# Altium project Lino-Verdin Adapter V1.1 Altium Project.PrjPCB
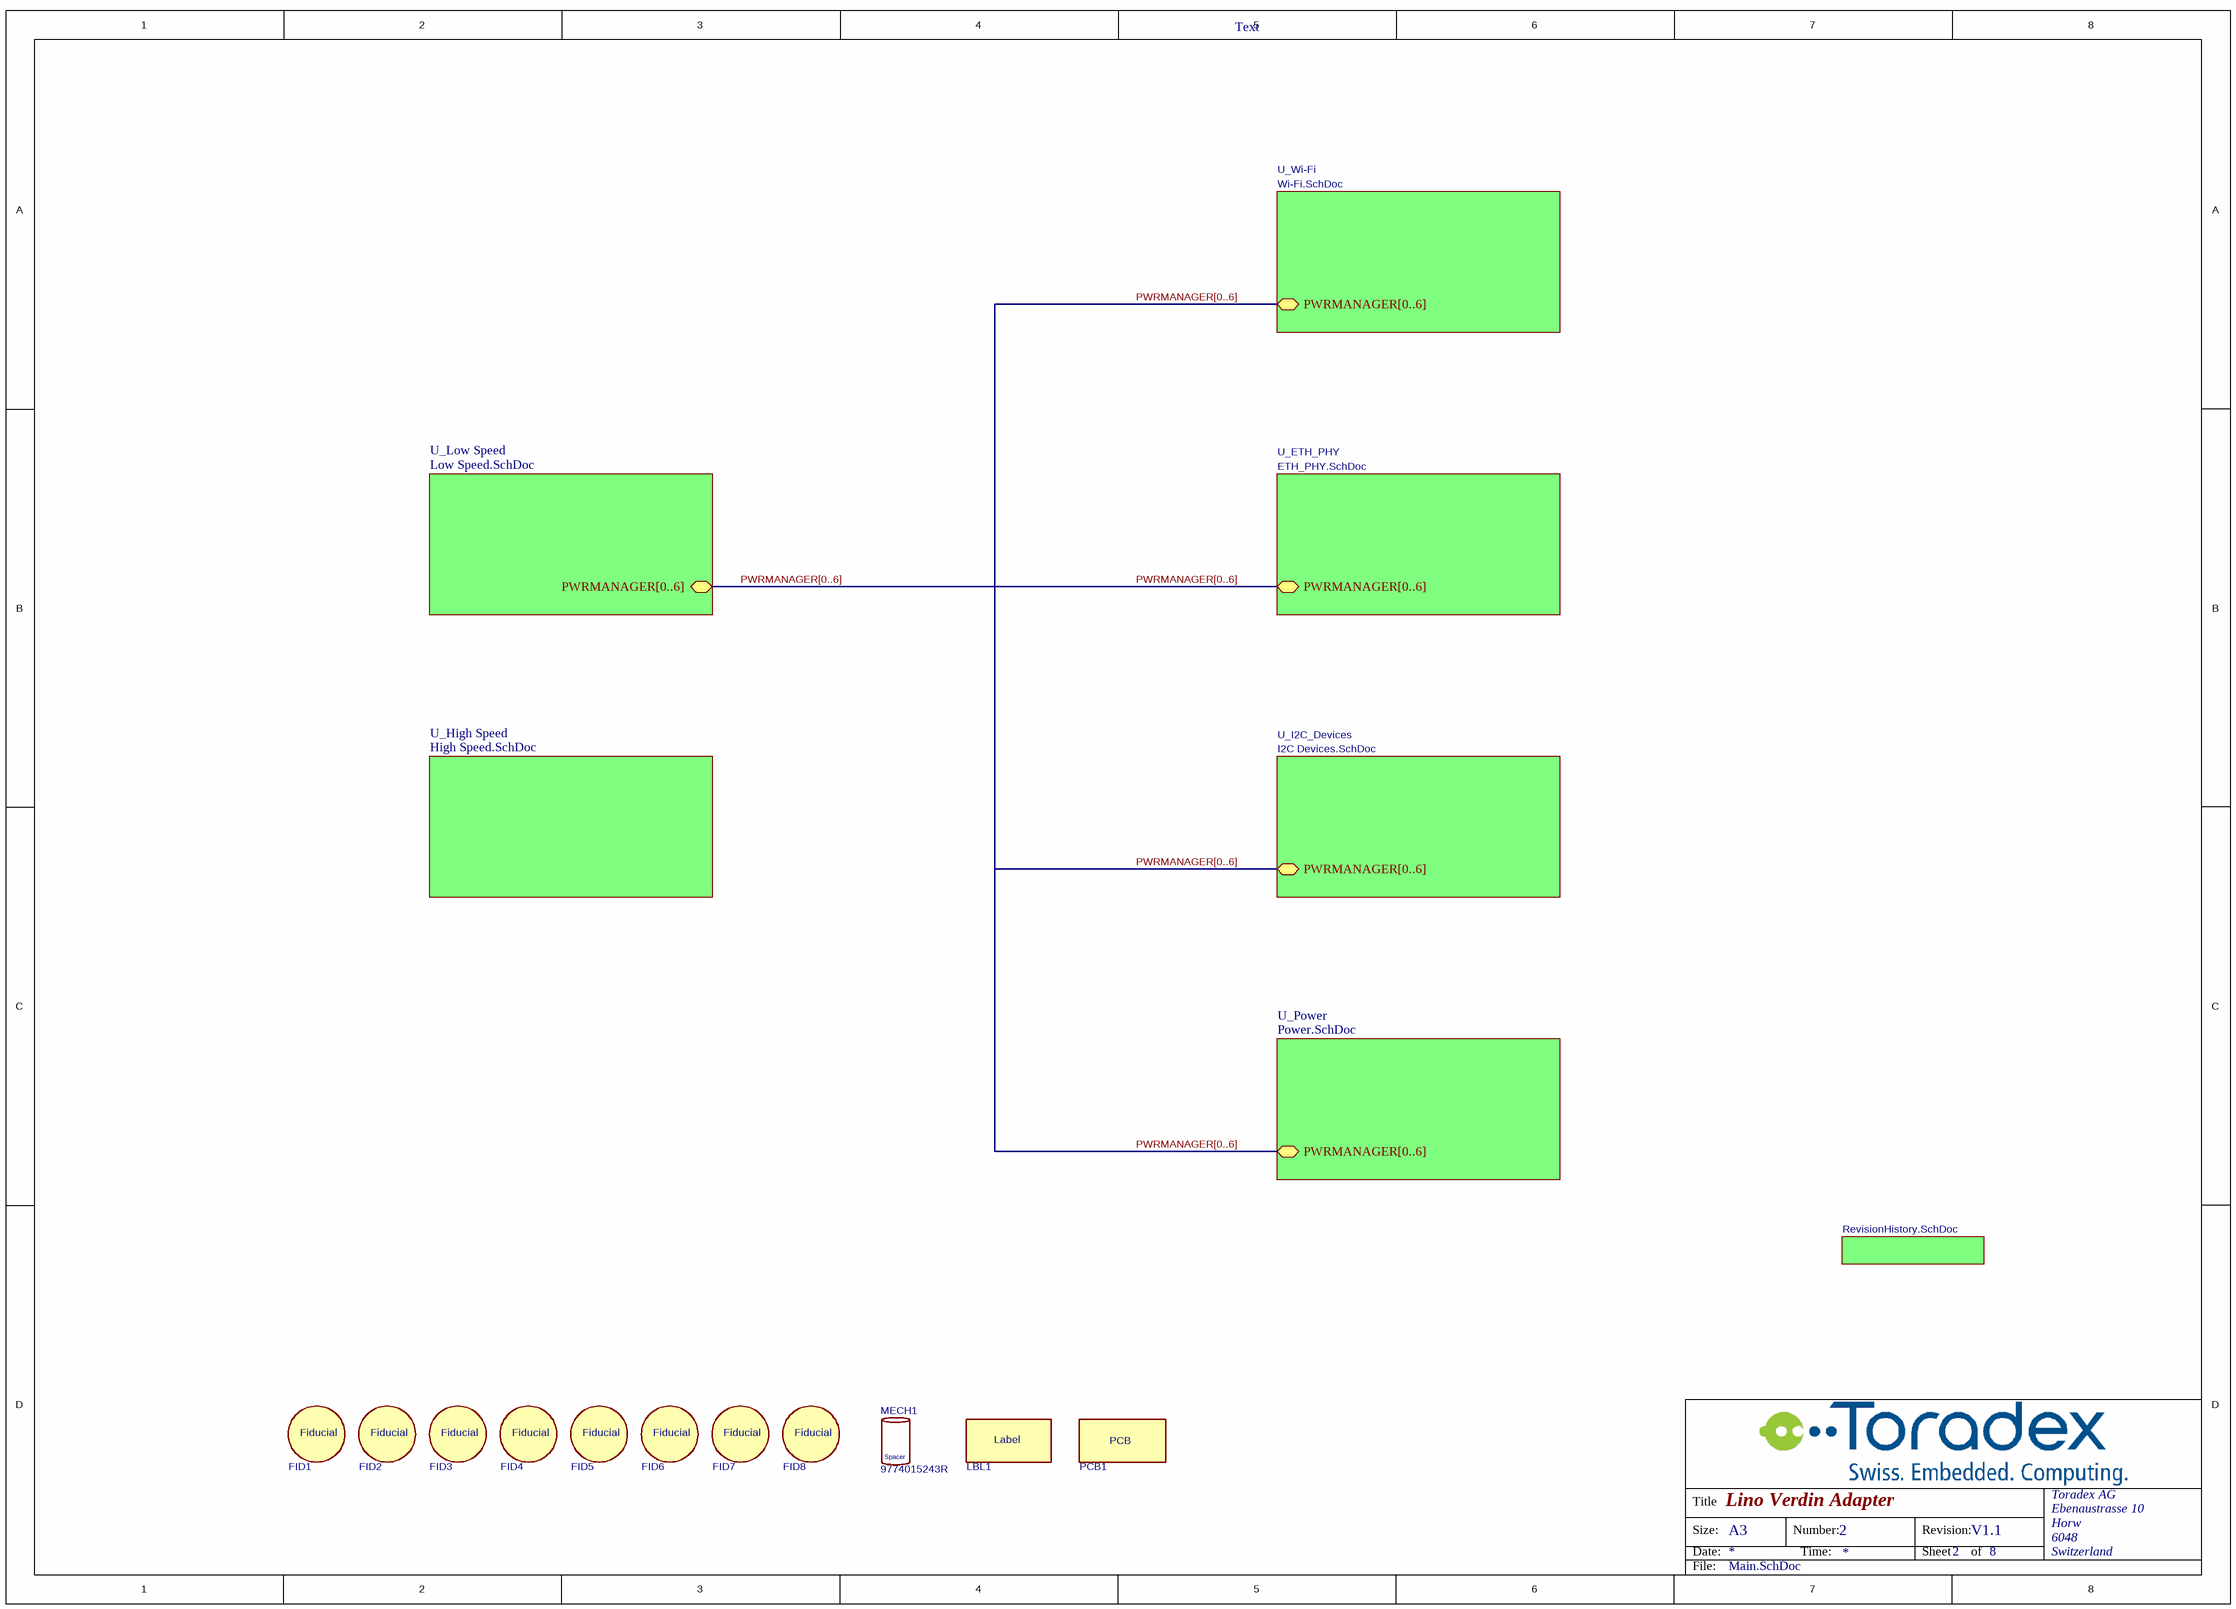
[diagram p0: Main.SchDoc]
5 sheets, 106 parts. Net scope: global (net labels, ports and power ports of the same name join across sheets).
Board file: Lino Verdin Adapter.PcbDoc
Sheets:
  Main.SchDoc
    U_ETH_PHY = ETH_PHY.SchDoc
    U_Wi-Fi = Wi-Fi.SchDoc
    U_Hist = RevisionHistory.SchDoc
    U_I2C_Devices = I2C Devices.SchDoc

## Sheet Main.SchDoc: Lino Verdin Adapter
size A3; Organization: Toradex AG; Address1: Ebenaustrasse 10; Address2: Horw; Address3: 6048; Address4: Switzerland; DocumentNumber: 2; Revision: V1.1; SheetNumber: 2; SheetTotal: 8; PageSetup: Record=PageOptions¦CenterHorizontal=True¦CenterVertical=True¦PrintScale=0.73¦XCorrection=1.00¦YCorrection=1.00¦PrintKind=0¦BorderSize=5000000¦LeftOffset=0¦BottomOffset=0¦Orientation=2¦PaperLength=1000¦PaperWidth=1000¦Scale=100¦PaperSource=7¦PrintQuality=-4¦MediaType=1¦DitherType=10¦PaperKind=A4¦PrintScaleMode=1

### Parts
FID1  MECH-Fiducial  [MECH-Fiducial_Round]  (value not drawn)  (no BOM)
FID2  MECH-Fiducial  [MECH-Fiducial_Round]  (value not drawn)  (no BOM)
FID3  MECH-Fiducial  [MECH-Fiducial_Round]  (value not drawn)  (no BOM)
FID4  MECH-Fiducial  [MECH-Fiducial_Round]  (value not drawn)  (no BOM)
FID5  MECH-Fiducial  [MECH-Fiducial_Round]  (value not drawn)  (no BOM)
FID6  MECH-Fiducial  [MECH-Fiducial_Round]  (value not drawn)  (no BOM)
FID7  MECH-Fiducial  [MECH-Fiducial_Round]  (value not drawn)  (no BOM)
FID8  MECH-Fiducial  [MECH-Fiducial_Round]  (value not drawn)  (no BOM)
LBL1  MECH-Label-Verdin_Lino_Adapter_V1.0A  (value not drawn)  (mechanical)
MECH1  Manufacturer Part No.: 9774015243R  [MECH-Wurth-9774015243R-Shaved-Pad-for-Lino]  (hidden comment: MECH-Wurth-9774015243R)
PCB1  MECH-PCB Verdin Lino Adapter V1.0.001  (value not drawn)  (mechanical)

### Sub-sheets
U_ETH_PHY = ETH_PHY.SchDoc: PWRMANAGER[0..6] (bidir)
U_High Speed = High Speed.SchDoc (file not in this document): no entries
U_Hist = RevisionHistory.SchDoc: no entries
U_I2C_Devices = I2C Devices.SchDoc: PWRMANAGER[0..6] (bidir)
U_Low Speed = Low Speed.SchDoc (file not in this document): PWRMANAGER[0..6] (bidir)
U_Power = Power.SchDoc (file not in this document): PWRMANAGER[0..6] (bidir)
U_Wi-Fi = Wi-Fi.SchDoc: PWRMANAGER[0..6] (bidir)

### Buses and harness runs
bus PWRMANAGER[0..6] = sheet U_ETH_PHY/PWRMANAGER[0..6] = sheet U_I2C_Devices/PWRMANAGER[0..6] = sheet U_Low Speed/PWRMANAGER[0..6] = sheet U_Power/PWRMANAGER[0..6] = sheet U_Wi-Fi/PWRMANAGER[0..6]

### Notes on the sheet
- Text

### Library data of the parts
FID1-FID8 = CMP-00203-11: Fiducial
LBL1 = CMP-00983-2: Generic Barcode Label; Manufacturer Part No.: Label: "Verdin Lino Adapter V1.0A 01851000+serial"
MECH1 = CMP-00975-3: Round Standoff M2x0.4 (1.50mm height); Manufacturer Name: Wurth
PCB1 = CMP-00984-1: PCB Structure; Manufacturer Name: Generic

## Sheet ETH_PHY.SchDoc: Lino Verdin Adapter
size A3; Organization: Toradex AG; Address1: Ebenaustrasse 10; Address2: Horw; Address3: 6048; Address4: Switzerland; DocumentNumber: 7; Revision: V1.1; SheetNumber: 7; SheetTotal: 8; PageSetup: Record=PageOptions¦CenterHorizontal=True¦CenterVertical=True¦PrintScale=0.73¦XCorrection=1.00¦YCorrection=1.00¦PrintKind=0¦BorderSize=5000000¦LeftOffset=0¦BottomOffset=0¦Orientation=2¦PaperLength=1000¦PaperWidth=1000¦Scale=100¦PaperSource=7¦PrintQuality=-4¦MediaType=1¦DitherType=10¦PaperKind=A4¦PrintScaleMode=1
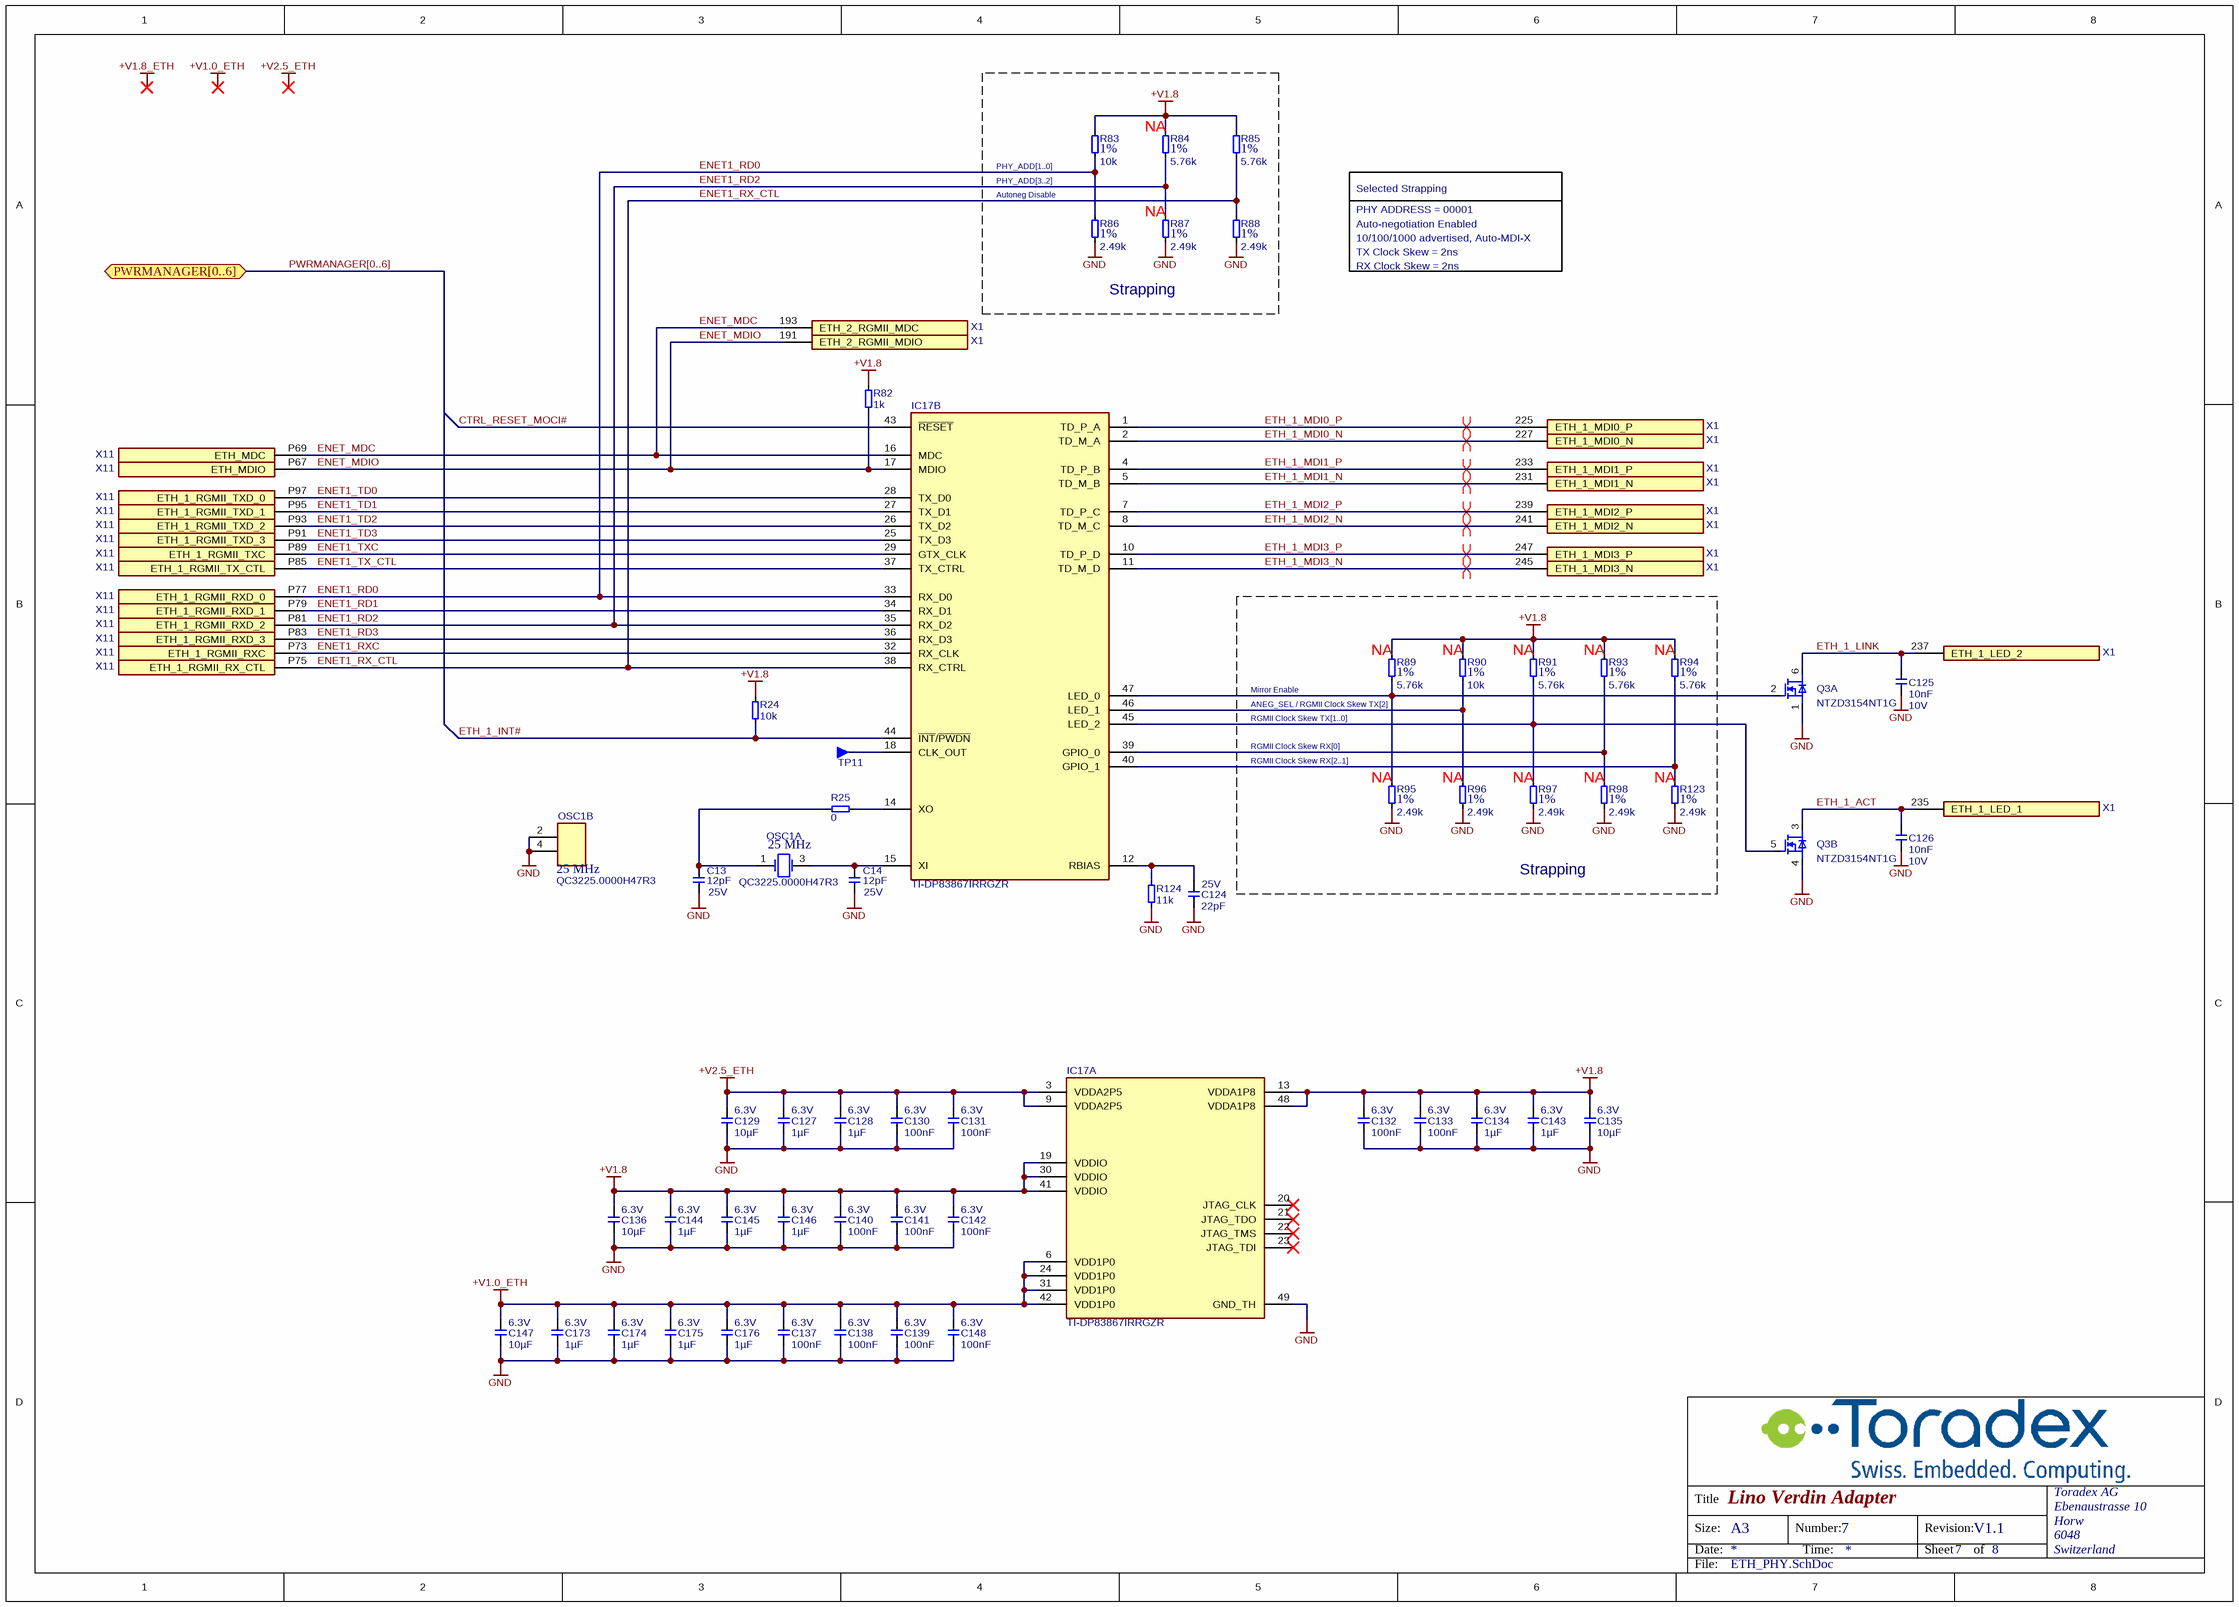
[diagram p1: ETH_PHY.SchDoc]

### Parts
C13  value 12pF  Rating: 25V  [CAPC60X30X33L15L]  (hidden comment: C-NP0-12p-25V-5%-0201)
C14  value 12pF  Rating: 25V  [CAPC60X30X33L15L]  (hidden comment: C-NP0-12p-25V-5%-0201)
C124  value 22pF  Rating: 25V  [CAPC60X30X33L15L]  (hidden comment: C-NP0-22p-25V-5%-0201)
C125  value 10nF  Rating: 10V  [CAPC60X30X33L15L]  (hidden comment: C-X7R-10n-10V-10%-0201)
C126  value 10nF  Rating: 10V  [CAPC60X30X33L15L]  (hidden comment: C-X7R-10n-10V-10%-0201)
C127  value 1µF  Rating: 6.3V  [CAPC60X30X33L15L]  (hidden comment: C-X5R-1u-6.3V-20%-0201)
C128  value 1µF  Rating: 6.3V  [CAPC60X30X33L15L]  (hidden comment: C-X5R-1u-6.3V-20%-0201)
C129  value 10µF  Rating: 6.3V  [CAPC100X50X60L25L]  (hidden comment: C-X5R-10u-6.3V-20%-0402)
C130  value 100nF  Rating: 6.3V  [CAPC60X30X33L15L]  (hidden comment: C-X5R-100n-6.3V-10%-0201)
C131  value 100nF  Rating: 6.3V  [CAPC60X30X33L15L]  (hidden comment: C-X5R-100n-6.3V-10%-0201)
C132  value 100nF  Rating: 6.3V  [CAPC60X30X33L15L]  (hidden comment: C-X5R-100n-6.3V-10%-0201)
C133  value 100nF  Rating: 6.3V  [CAPC60X30X33L15L]  (hidden comment: C-X5R-100n-6.3V-10%-0201)
C134  value 1µF  Rating: 6.3V  [CAPC60X30X33L15L]  (hidden comment: C-X5R-1u-6.3V-20%-0201)
C135  value 10µF  Rating: 6.3V  [CAPC100X50X60L25L]  (hidden comment: C-X5R-10u-6.3V-20%-0402)
C136  value 10µF  Rating: 6.3V  [CAPC100X50X60L25L]  (hidden comment: C-X5R-10u-6.3V-20%-0402)
C137  value 100nF  Rating: 6.3V  [CAPC60X30X33L15L]  (hidden comment: C-X5R-100n-6.3V-10%-0201)
C138  value 100nF  Rating: 6.3V  [CAPC60X30X33L15L]  (hidden comment: C-X5R-100n-6.3V-10%-0201)
C139  value 100nF  Rating: 6.3V  [CAPC60X30X33L15L]  (hidden comment: C-X5R-100n-6.3V-10%-0201)
C140  value 100nF  Rating: 6.3V  [CAPC60X30X33L15L]  (hidden comment: C-X5R-100n-6.3V-10%-0201)
C141  value 100nF  Rating: 6.3V  [CAPC60X30X33L15L]  (hidden comment: C-X5R-100n-6.3V-10%-0201)
C142  value 100nF  Rating: 6.3V  [CAPC60X30X33L15L]  (hidden comment: C-X5R-100n-6.3V-10%-0201)
C143  value 1µF  Rating: 6.3V  [CAPC60X30X33L15L]  (hidden comment: C-X5R-1u-6.3V-20%-0201)
C144  value 1µF  Rating: 6.3V  [CAPC60X30X33L15L]  (hidden comment: C-X5R-1u-6.3V-20%-0201)
C145  value 1µF  Rating: 6.3V  [CAPC60X30X33L15L]  (hidden comment: C-X5R-1u-6.3V-20%-0201)
C146  value 1µF  Rating: 6.3V  [CAPC60X30X33L15L]  (hidden comment: C-X5R-1u-6.3V-20%-0201)
C147  value 10µF  Rating: 6.3V  [CAPC100X50X60L25L]  (hidden comment: C-X5R-10u-6.3V-20%-0402)
C148  value 100nF  Rating: 6.3V  [CAPC60X30X33L15L]  (hidden comment: C-X5R-100n-6.3V-10%-0201)
C173  value 1µF  Rating: 6.3V  [CAPC60X30X33L15L]  (hidden comment: C-X5R-1u-6.3V-20%-0201)
C174  value 1µF  Rating: 6.3V  [CAPC60X30X33L15L]  (hidden comment: C-X5R-1u-6.3V-20%-0201)
C175  value 1µF  Rating: 6.3V  [CAPC60X30X33L15L]  (hidden comment: C-X5R-1u-6.3V-20%-0201)
C176  value 1µF  Rating: 6.3V  [CAPC60X30X33L15L]  (hidden comment: C-X5R-1u-6.3V-20%-0201)
IC17  TI-DP83867IRRGZR  [QFN48P50_700X700X100L60X24T410X410 - SoM]  (parts A,B of 2)
OSC1  value 25 MHz  Manufacturer Part No.: QC3225.0000H47R3  [OSC-SMD-3.2mmx2.5mm]  (hidden comment: OSC-QANTEK-QC3225.0000H47R3)  (parts A,B of 2)
Q3  Manufacturer Part No.: NTZD3154NT1G  [SOT563-6P50_160X60L30N]  (hidden comment: 2N MOSFET)  (parts A,B of 2)
R24  value 10k  [RESC60X30X33L15L]  (hidden comment: R-10K-50mW-1%-0201)
R25  value 0  [RESC60X30X33L15L]  (hidden comment: R-0R-50mW-5%-0201)
R82  value 1k  [RESC60X30X33L15L]  (hidden comment: R-1K-50mW-5%-0201)
R83  value 10k  Tolerance: 1%  [RESC60X30X33L15L]  (hidden comment: R-10K-50mW-1%-0201)
R84  value 5.76k  Tolerance: 1%  [RESC60X30X33L15L]  (hidden comment: R-5.76K-50mW-1%-0201)
R85  value 5.76k  Tolerance: 1%  [RESC60X30X33L15L]  (hidden comment: R-5.76K-50mW-1%-0201)
R86  value 2.49k  Tolerance: 1%  [RESC60X30X33L15L]  (hidden comment: R-2.49K-50mW-1%-0201)
R87  value 2.49k  Tolerance: 1%  [RESC60X30X33L15L]  (hidden comment: R-2.49K-50mW-1%-0201)
R88  value 2.49k  Tolerance: 1%  [RESC60X30X33L15L]  (hidden comment: R-2.49K-50mW-1%-0201)
R89  value 5.76k  Tolerance: 1%  [RESC60X30X33L15L]  (hidden comment: R-5.76K-50mW-1%-0201)
R90  value 10k  Tolerance: 1%  [RESC60X30X33L15L]  (hidden comment: R-10K-50mW-1%-0201)
R91  value 5.76k  Tolerance: 1%  [RESC60X30X33L15L]  (hidden comment: R-5.76K-50mW-1%-0201)
R93  value 5.76k  Tolerance: 1%  [RESC60X30X33L15L]  (hidden comment: R-5.76K-50mW-1%-0201)
R94  value 5.76k  Tolerance: 1%  [RESC60X30X33L15L]  (hidden comment: R-5.76K-50mW-1%-0201)
R95  value 2.49k  Tolerance: 1%  [RESC60X30X33L15L]  (hidden comment: R-2.49K-50mW-1%-0201)
R96  value 2.49k  Tolerance: 1%  [RESC60X30X33L15L]  (hidden comment: R-2.49K-50mW-1%-0201)
R97  value 2.49k  Tolerance: 1%  [RESC60X30X33L15L]  (hidden comment: R-2.49K-50mW-1%-0201)
R98  value 2.49k  Tolerance: 1%  [RESC60X30X33L15L]  (hidden comment: R-2.49K-50mW-1%-0201)
R123  value 2.49k  Tolerance: 1%  [RESC60X30X33L15L]  (hidden comment: R-2.49K-50mW-1%-0201)
R124  value 11k  [RESC60X30X33L15L]  (hidden comment: R-11K-50mW-1%-0201)
TP11  #TestPin_SMD-0.50mm#_NoPaste  [Pad_SMT_Round_0.5_NoSilk_NoPaste]  (value not drawn)  (no BOM)
X1  CON-SODIMM-DDR4-TEST  [SODIMM_DDR4_no_Module]  (value not drawn)  (parts 118,119,134,135,137,138,139,140,141,142,144,145 of 260)  (no BOM)
X11  CON-LINO-P-CARRIER  [HIROSE_DF40C_100DS_LINO_CARRIER_PRIMARY]  (value not drawn)  (parts 34,35,37,38,39,40,41,42,43,45,46,47,48,49 of 100)

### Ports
PWRMANAGER[0..6] (bidir)

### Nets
+V1.0_ETH: C137.2 C138.2 C139.2 C147.2 C148.2 C173.2 C174.2 C175.2 C176.2 IC17.6(VDD1P0) IC17.24(VDD1P0) IC17.31(VDD1P0) IC17.42(VDD1P0)
+V1.8: C132.2 C133.2 C134.2 C135.2 C136.2 C140.2 C141.2 C142.2 C143.2 C144.2 C145.2 C146.2 IC17.13(VDDA1P8) IC17.19(VDDIO) IC17.30(VDDIO) IC17.41(VDDIO) IC17.48(VDDA1P8) R24.2 R82.2 R83.2 R84.2 R85.2 R89.2 R90.2 R91.2 R93.2 R94.2
+V2.5_ETH: C127.2 C128.2 C129.2 C130.2 C131.2 IC17.3(VDDA2P5) IC17.9(VDDA2P5)
GND: C13.1 C14.1 C124.1 C125.2 C126.2 C127.1 C128.1 C129.1 C130.1 C131.1 C132.1 C133.1 C134.1 C135.1 C136.1 C137.1 C138.1 C139.1 C140.1 C141.1 C142.1 C143.1 C144.1 C145.1 C146.1 C147.1 C148.1 C173.1 C174.1 C175.1 C176.1 IC17.49(GND_TH) OSC1.2(OSC2) OSC1.4(OSC3) Q3.1(S) Q3.4(S) R86.1 R87.1 R88.1 R95.1 R96.1 R97.1 R98.1 R123.1 R124.1
CTRL_RESET_MOCI#: IC17.43(~{RESET})
ENET1_RD0: IC17.33(RX_D0) R83.1 R86.2 X11.P77(ETH_1_RGMII_RXD_0)
ENET1_RD1: IC17.34(RX_D1) X11.P79(ETH_1_RGMII_RXD_1)
ENET1_RD2: IC17.35(RX_D2) R84.1 R87.2 X11.P81(ETH_1_RGMII_RXD_2)
ENET1_RD3: IC17.36(RX_D3) X11.P83(ETH_1_RGMII_RXD_3)
ENET1_RX_CTL: IC17.38(RX_CTRL) R85.1 R88.2 X11.P75(ETH_1_RGMII_RX_CTL)
ENET1_RXC: IC17.32(RX_CLK) X11.P73(ETH_1_RGMII_RXC)
ENET1_TD0: IC17.28(TX_D0) X11.P97(ETH_1_RGMII_TXD_0)
ENET1_TD1: IC17.27(TX_D1) X11.P95(ETH_1_RGMII_TXD_1)
ENET1_TD2: IC17.26(TX_D2) X11.P93(ETH_1_RGMII_TXD_2)
ENET1_TD3: IC17.25(TX_D3) X11.P91(ETH_1_RGMII_TXD_3)
ENET1_TX_CTL: IC17.37(TX_CTRL) X11.P85(ETH_1_RGMII_TX_CTL)
ENET1_TXC: IC17.29(GTX_CLK) X11.P89(ETH_1_RGMII_TXC)
ENET_MDC: IC17.16(MDC) X1.193(ETH_2_RGMII_MDC) X11.P69(ETH_MDC)
ENET_MDIO: IC17.17(MDIO) R82.1 X1.191(ETH_2_RGMII_MDIO) X11.P67(ETH_MDIO)
ETH_1_ACT: C126.1 Q3.3(D) X1.235(ETH_1_LED_1)
ETH_1_INT#: IC17.44(~{INT}/~{PWDN}) R24.1
ETH_1_LINK: C125.1 Q3.6(D) X1.237(ETH_1_LED_2)
ETH_1_MDI0_N: IC17.2(TD_M_A) X1.227(ETH_1_MDI0_N)
ETH_1_MDI0_P: IC17.1(TD_P_A) X1.225(ETH_1_MDI0_P)
ETH_1_MDI1_N: IC17.5(TD_M_B) X1.231(ETH_1_MDI1_N)
ETH_1_MDI1_P: IC17.4(TD_P_B) X1.233(ETH_1_MDI1_P)
ETH_1_MDI2_N: IC17.8(TD_M_C) X1.241(ETH_1_MDI2_N)
ETH_1_MDI2_P: IC17.7(TD_P_C) X1.239(ETH_1_MDI2_P)
ETH_1_MDI3_N: IC17.11(TD_M_D) X1.245(ETH_1_MDI3_N)
ETH_1_MDI3_P: IC17.10(TD_P_D) X1.247(ETH_1_MDI3_P)
NetC13_2: C13.2 OSC1.1(OSC1) R25.1
NetC14_2: C14.2 IC17.15(XI) OSC1.3(OSC2)
NetC124_2: C124.2 IC17.12(RBIAS) R124.2
NetIC17_14: IC17.14(XO) R25.2
NetIC17_18: IC17.18(CLK_OUT) TP11.1
NetIC17_39: IC17.39(GPIO_0) R93.1 R98.2
NetIC17_40: IC17.40(GPIO_1) R94.1 R123.2
NetIC17_45: IC17.45(LED_2) Q3.5(G) R91.1 R97.2
NetIC17_46: IC17.46(LED_1) R90.1 R96.2
NetIC17_47: IC17.47(LED_0) Q3.2(G) R89.1 R95.2

Not connected (* = marked no-connect by the designer): IC17 20(JTAG_CLK)* 21(JTAG_TDO)* 22(JTAG_TMS)* 23(JTAG_TDI)*

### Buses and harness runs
bus PWRMANAGER[0..6] = port PWRMANAGER[0..6]

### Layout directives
differential pair: ETH_1_MDI0_N, ETH_1_MDI0_P, ETH_1_MDI1_N, ETH_1_MDI1_P, ETH_1_MDI2_N, ETH_1_MDI2_P, ETH_1_MDI3_N, ETH_1_MDI3_P

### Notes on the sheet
- PHY_ADD[1..0]
- PHY_ADD[3..2]
- (near R84) NA
- Selected Strapping
- Autoneg Disable
- (near R87) NA
- PHY ADDRESS = 00001
- Auto-negotiation Enabled
- 10/100/1000 advertised, Auto-MDI-X
- TX Clock Skew = 2ns
- RX Clock Skew = 2ns
- Strapping
- Mirror Enable
- (near R89) NA
- (near R90) NA
- (near R91) NA
- (near R93) NA
- (near R94) NA
- RGMII Clock Skew RX[0]
- (near R89) ANEG_SEL / RGMII Clock Skew TX[2]
- RGMII Clock Skew TX[1..0]
- (near R95) RGMII Clock Skew RX[2..1]
- (near R95) NA
- (near R96) NA
- (near R97) NA
- (near R98) NA
- (near R123) NA
- Labels drawn without touching a wire or pin: +V1.0_ETH, +V1.8_ETH, +V2.5_ETH

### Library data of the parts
C13 C14 = CMP-00458-9: Capacitor Ceramic NP0 12pF 25V 5% 0201; Manufacturer Name: Generic
C124 = CMP-00459-10: Capacitor Ceramic NP0 22pF 25V 5% 0201; Manufacturer Name: Generic
C125 C126 = CMP-00468-10: Capacitor Ceramic X7R 10nF 10V 10% 0201; Manufacturer Name: Generic
C127 C128 C134 C143-C146 C173-C176 = CMP-00466-9: Capacitor Ceramic X5R 1uF 6.3V 20% 0201; Manufacturer Name: Generic
C129 C135 C136 C147 = CMP-00249-13: Capacitor Ceramic X5R 10uF 6.3V 20% 0402; Manufacturer Name: Generic
C130-C133 C137-C142 C148 = CMP-00475-11: Capacitor Ceramic X5R 100nF 6.3V 20% 0201; Manufacturer Name: Generic; Tolerance: 10%
IC17 = CMP-00505-11: Gigabit Ethernet Transceiver with RGMII (DP83867, QFN-48 (7mmx7mm) Leadless, -40C to +85C; Manufacturer Name: Texas Instruments
OSC1 = CMP-00208-13: 25MHz Crystal, 3.2x2.5mm, 20ppm, 10pF, 40 Ohm, -40C to +85C; Manufacturer Name: Qantek; Frequency Tolerance: 20; ESR: 40
Q3 = CMP-00121-16: Dual N-Channel 20V (D-S)  MOSFET, 20 V, 540 mA, SOT−563; Manufacturer Name: onsemi; Drain-source On Resistance-Max: 0.55; Drain Current-Max (ID): 540mA
R24 R83 R90 = CMP-00426-16: Resistor 10K ohm 50mW 1% 0201; Manufacturer Name: Generic
R25 = CMP-00402-19: Resistor 0 ohm 50mW 5% 0201; Manufacturer Name: Generic
R82 = CMP-00424-15: Resistor 1K ohm 50mW 5% 0201; Manufacturer Name: Generic
R84 R85 R89 R91 R93 R94 = CMP-00456-14: Resistor 5.76K ohm 50mW 1% 0201; Manufacturer Name: Generic
R86-R88 R95-R98 R123 = CMP-00452-14: Resistor 2.49K ohm 50mW 1% 0201; Manufacturer Name: Generic
R124 = CMP-00429-14: Resistor 11K ohm 50mW 1% 0201; Manufacturer Name: Generic
TP11 = CMP-00566-8: Testpin Round 0.5mm; Manufacturer Name: Generic
X1 = CMP-00731-8: DDR4 SODIMM Card Edge, 260 pins, 0.5mm Pitch; Manufacturer Name: Generic; Manufacturer Part No.: No Physical Component; Gender: Male
X11 = CMP-00961-5: LINO Primary Connector Carrier; Manufacturer Name: Amphenol; Manufacturer Part No.: 10164227-1001A1RLF; Rows: 2

## Sheet Wi-Fi.SchDoc: Lino Verdin Adapter
size A3; Organization: Toradex AG; Address1: Ebenaustrasse 10; Address2: Horw; Address3: 6048; Address4: Switzerland; DocumentNumber: 8; Revision: V1.1; SheetNumber: 8; SheetTotal: 8; PageSetup: Record=PageOptions¦CenterHorizontal=True¦CenterVertical=True¦PrintScale=0.73¦XCorrection=1.00¦YCorrection=1.00¦PrintKind=0¦BorderSize=5000000¦LeftOffset=0¦BottomOffset=0¦Orientation=2¦PaperLength=1000¦PaperWidth=1000¦Scale=100¦PaperSource=7¦PrintQuality=-4¦MediaType=1¦DitherType=10¦PaperKind=A4¦PrintScaleMode=1
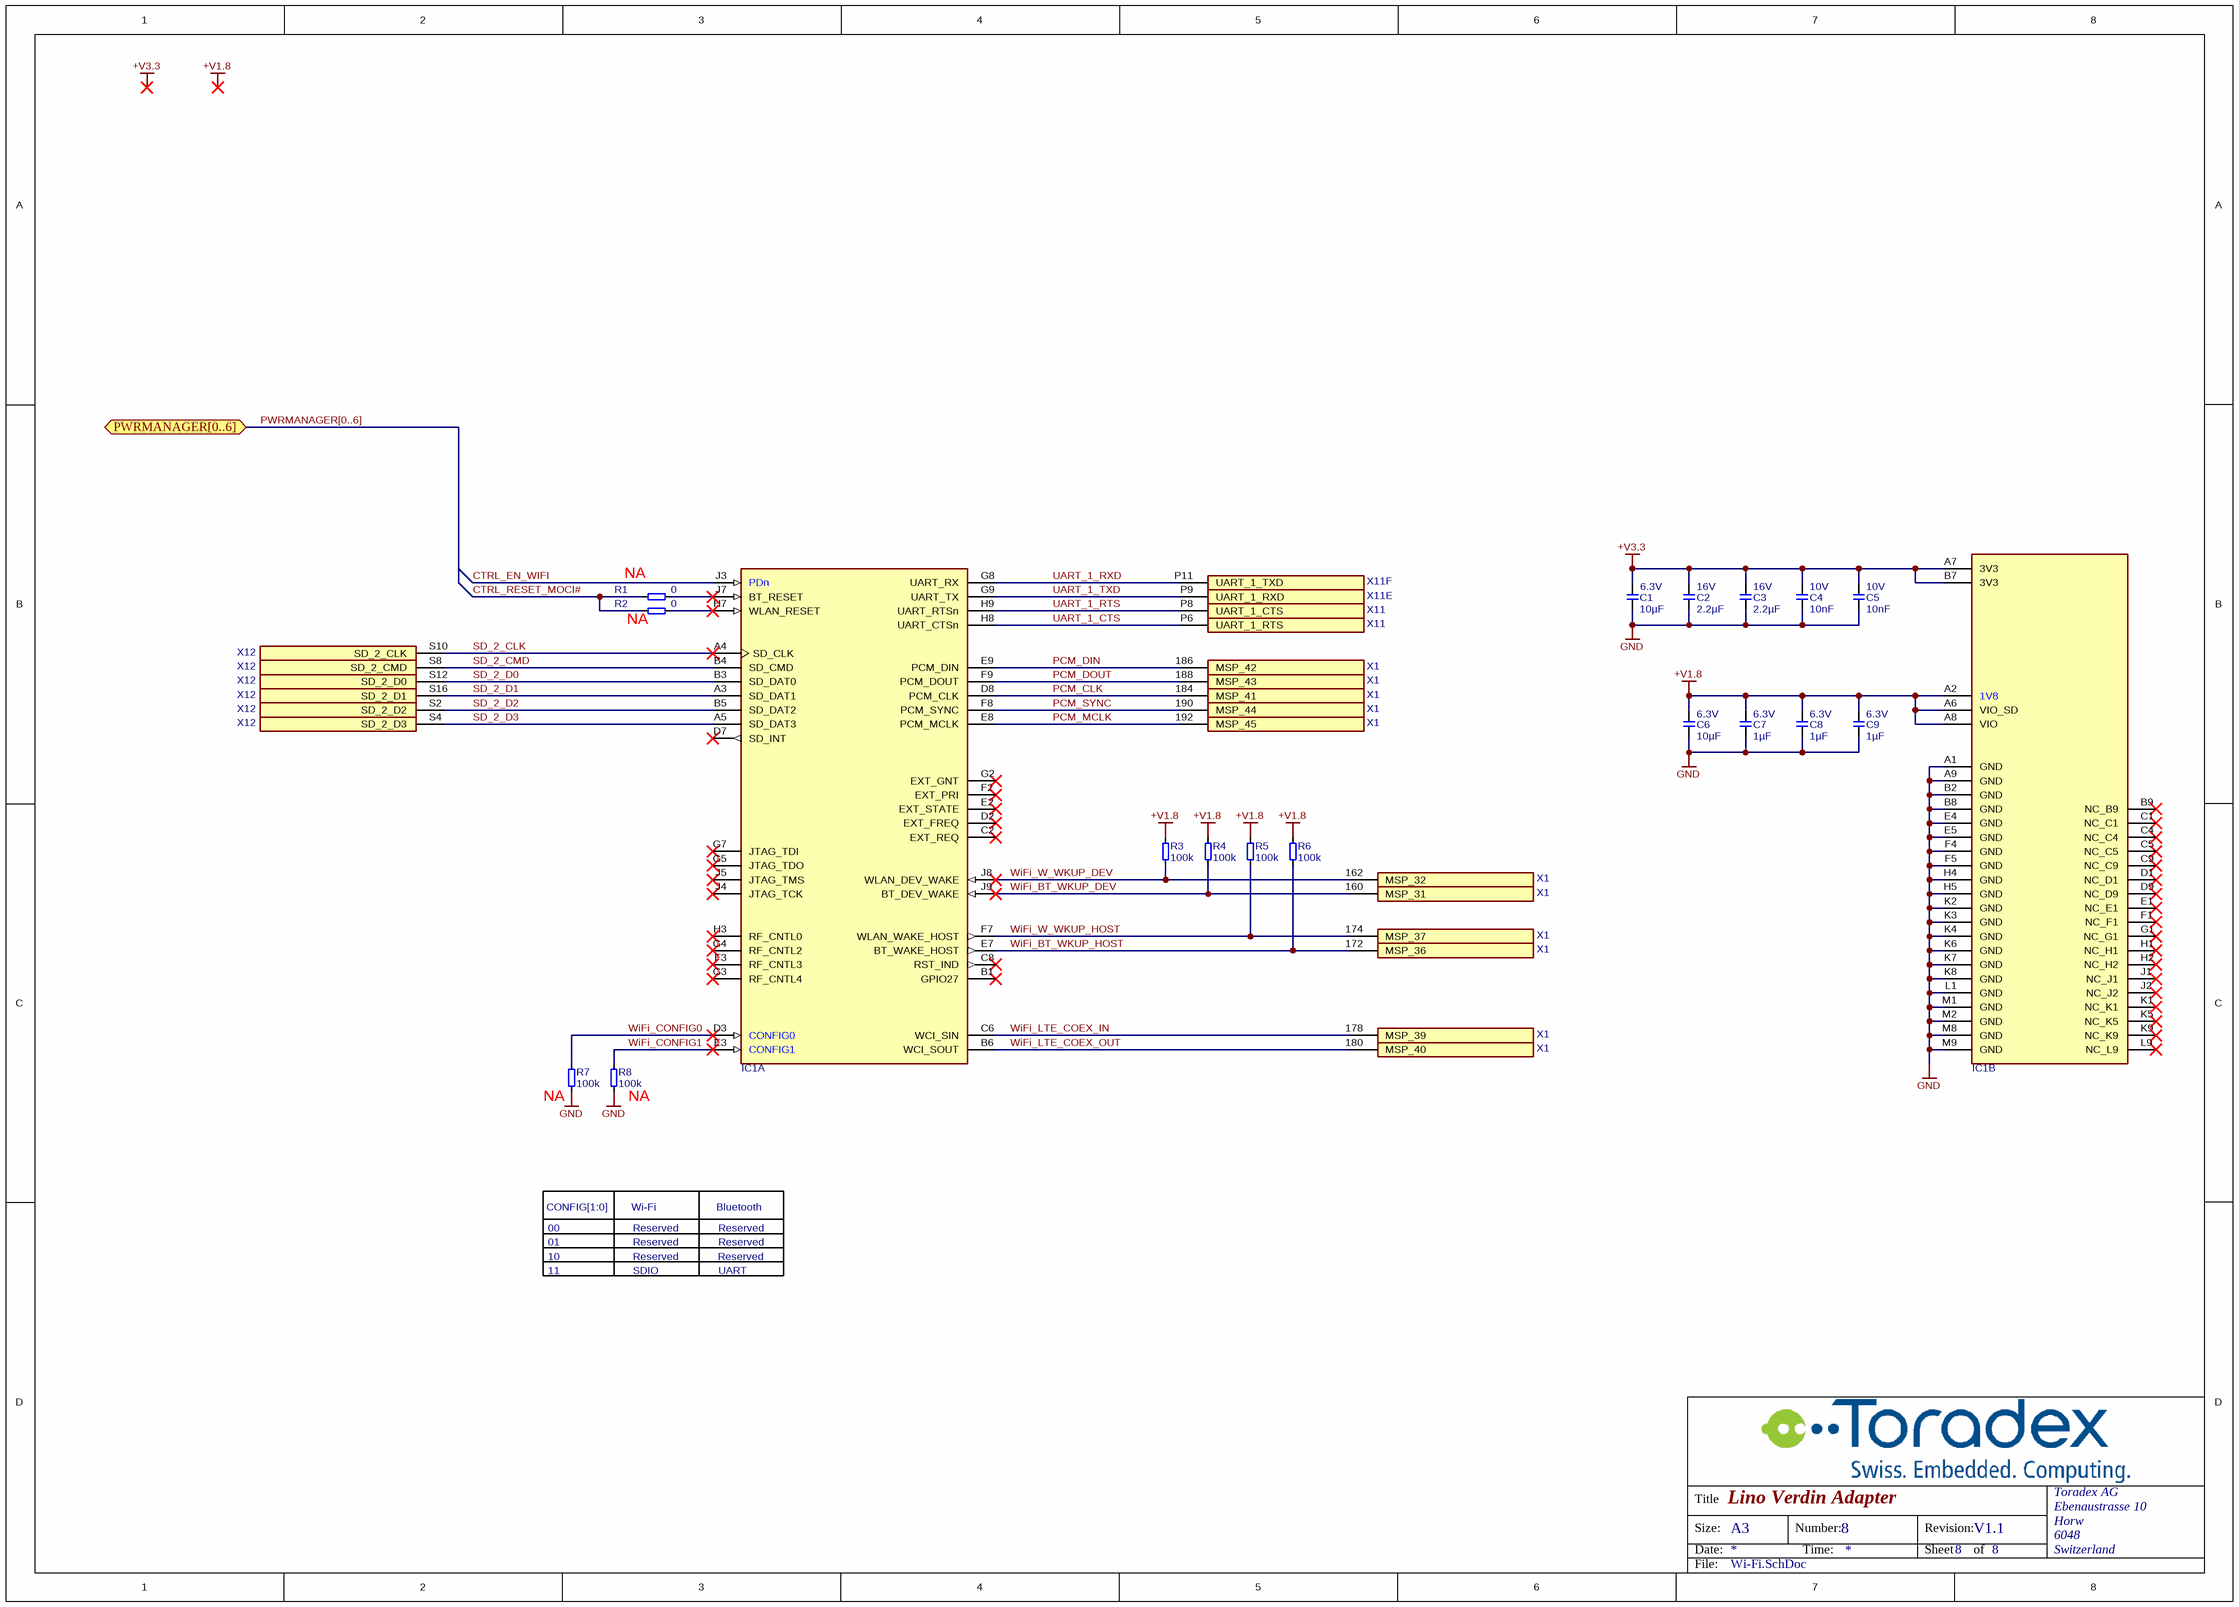
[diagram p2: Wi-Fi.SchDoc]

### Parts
C1  value 10µF  Rating: 6.3V  [CAPC100X50X60L25L]  (hidden comment: C-X5R-10u-6.3V-20%-0402)
C2  value 2.2µF  Rating: 16V  [CAPC100X50X60L25L]  (hidden comment: C-X5R-2.2u-16V-20%-0402)
C3  value 2.2µF  Rating: 16V  [CAPC100X50X60L25L]  (hidden comment: C-X5R-2.2u-16V-20%-0402)
C4  value 10nF  Rating: 10V  [CAPC60X30X33L15L]  (hidden comment: C-X7R-10n-10V-10%-0201)
C5  value 10nF  Rating: 10V  [CAPC60X30X33L15L]  (hidden comment: C-X7R-10n-10V-10%-0201)
C6  value 10µF  Rating: 6.3V  [CAPC100X50X60L25L]  (hidden comment: C-X5R-10u-6.3V-20%-0402)
C7  value 1µF  Rating: 6.3V  [CAPC60X30X33L15L]  (hidden comment: C-X5R-1u-6.3V-20%-0201)
C8  value 1µF  Rating: 6.3V  [CAPC60X30X33L15L]  (hidden comment: C-X5R-1u-6.3V-20%-0201)
C9  value 1µF  Rating: 6.3V  [CAPC60X30X33L15L]  (hidden comment: C-X5R-1u-6.3V-20%-0201)
IC1  IC_UBLOX_MAYA-W260-00B  [UBLOX_MAYA-W1/W2]  (value not drawn)  (parts A,B of 2)
R1  value 0  [RESC60X30X33L15L]  (hidden comment: R-0R-50mW-5%-0201)
R2  value 0  [RESC60X30X33L15L]  (hidden comment: R-0R-50mW-5%-0201)
R3  value 100k  [RESC60X30X33L15L]  (hidden comment: R-100K-50mW-1%-0201)
R4  value 100k  [RESC60X30X33L15L]  (hidden comment: R-100K-50mW-1%-0201)
R5  value 100k  [RESC60X30X33L15L]  (hidden comment: R-100K-50mW-1%-0201)
R6  value 100k  [RESC60X30X33L15L]  (hidden comment: R-100K-50mW-1%-0201)
R7  value 100k  [RESC60X30X33L15L]  (hidden comment: R-100K-50mW-1%-0201)
R8  value 100k  [RESC60X30X33L15L]  (hidden comment: R-100K-50mW-1%-0201)
X1  CON-SODIMM-DDR4-TEST  [SODIMM_DDR4_no_Module]  (value not drawn)  (parts I,228,229,234,236,237,239,240,241,242,243 of 260)  (no BOM)
X11  CON-LINO-P-CARRIER  [HIROSE_DF40C_100DS_LINO_CARRIER_PRIMARY]  (value not drawn)  (parts E,F,53,54 of 100)
X12  CON-LINO-S-CARRIER  [HIROSE_DF40C_100DS_LINO_CARRIER_SECONDARY]  (value not drawn)  (parts 51,52,54,55,56,58 of 100)

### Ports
PWRMANAGER[0..6] (bidir)

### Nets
+V1.8: C6.2 C7.2 C8.2 C9.2 IC1.A2(1V8) IC1.A6(VIO_SD) IC1.A8(VIO) R3.1 R4.1 R5.1 R6.1
+V3.3: C1.2 C2.2 C3.2 C4.2 C5.2 IC1.A7(3V3) IC1.B7(3V3)
GND: C1.1 C2.1 C3.1 C4.1 C5.1 C6.1 C7.1 C8.1 C9.1 IC1.A1(GND) IC1.A9(GND) IC1.B2(GND) IC1.B8(GND) IC1.E4(GND) IC1.E5(GND) IC1.F4(GND) IC1.F5(GND) IC1.H4(GND) IC1.H5(GND) IC1.K2(GND) IC1.K3(GND) IC1.K4(GND) IC1.K6(GND) IC1.K7(GND) IC1.K8(GND) IC1.L1(GND) IC1.M1(GND) IC1.M2(GND) IC1.M8(GND) IC1.M9(GND) R7.1 R8.1
CTRL_EN_WIFI: IC1.J3(PDn)
CTRL_RESET_MOCI#: R1.2 R2.2
PCM_CLK: IC1.D8(PCM_CLK) X1.184(MSP_41)
PCM_DIN: IC1.E9(PCM_DIN) X1.186(MSP_42)
PCM_DOUT: IC1.F9(PCM_DOUT) X1.188(MSP_43)
PCM_MCLK: IC1.E8(PCM_MCLK) X1.192(MSP_45)
PCM_SYNC: IC1.F8(PCM_SYNC) X1.190(MSP_44)
SD_2_CLK: IC1.A4(SD_CLK) X12.S10(SD_2_CLK)
SD_2_CMD: IC1.B4(SD_CMD) X12.S8(SD_2_CMD)
SD_2_D0: IC1.B3(SD_DAT0) X12.S12(SD_2_D0)
SD_2_D1: IC1.A3(SD_DAT1) X12.S16(SD_2_D1)
SD_2_D2: IC1.B5(SD_DAT2) X12.S2(SD_2_D2)
SD_2_D3: IC1.A5(SD_DAT3) X12.S4(SD_2_D3)
UART_1_CTS: IC1.H8(UART_CTSn) X11.P6(UART_1_RTS)
UART_1_RTS: IC1.H9(UART_RTSn) X11.P8(UART_1_CTS)
UART_1_RXD: IC1.G8(UART_RX) X11.P11(UART_1_TXD)
UART_1_TXD: IC1.G9(UART_TX) X11.P9(UART_1_RXD)
WiFi_BT_WKUP_DEV: IC1.J9(BT_DEV_WAKE) R4.2 X1.160(MSP_31)
WiFi_BT_WKUP_HOST: IC1.E7(BT_WAKE_HOST) R6.2 X1.172(MSP_36)
WiFi_CONFIG0: IC1.D3(CONFIG0) R7.2
WiFi_CONFIG1: IC1.E3(CONFIG1) R8.2
WiFi_LTE_COEX_IN: IC1.C6(WCI_SIN) X1.178(MSP_39)
WiFi_LTE_COEX_OUT: IC1.B6(WCI_SOUT) X1.180(MSP_40)
WiFi_W_WKUP_DEV: IC1.J8(WLAN_DEV_WAKE) R3.2 X1.162(MSP_32)
WiFi_W_WKUP_HOST: IC1.F7(WLAN_WAKE_HOST) R5.2 X1.174(MSP_37)
NetIC1_H7: IC1.H7(WLAN_RESET) R2.1
NetIC1_J7: IC1.J7(BT_RESET) R1.1

Not connected (* = marked no-connect by the designer): IC1 B1(GPIO27)* B9(NC_B9)* C1(NC_C1)* C2(EXT_REQ)* C4(NC_C4)* C5(NC_C5)* C8(RST_IND)* C9(NC_C9)* D1(NC_D1)* D2(EXT_FREQ)* D7(SD_INT)* D9(NC_D9)* E1(NC_E1)* E2(EXT_STATE)* F1(NC_F1)* F2(EXT_PRI)* F3(RF_CNTL3)* G1(NC_G1)* G2(EXT_GNT)* G3(RF_CNTL4)* G4(RF_CNTL2)* G5(JTAG_TDO)* G7(JTAG_TDI)* H1(NC_H1)* H2(NC_H2)* H3(RF_CNTL0)* J1(NC_J1)* J2(NC_J2)* J4(JTAG_TCK)* J5(JTAG_TMS)* K1(NC_K1)* K5(NC_K5)* K9(NC_K9)* L9(NC_L9)*

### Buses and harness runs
bus PWRMANAGER[0..6] = port PWRMANAGER[0..6]

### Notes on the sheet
- (near R1) NA
- (near R2) NA
- (near R7) NA
- (near R8) NA
- CONFIG[1:0]
- Wi-Fi
- Bluetooth
- 01
- 10
- 11
- 00
- Reserved
- SDIO
- UART
- Labels drawn without touching a wire or pin: +V1.8, +V3.3

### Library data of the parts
C1 C6 = CMP-00249-13: as C129 on sheet ETH_PHY
C2 C3 = CMP-00469-9: Capacitor Ceramic X5R 2.2uF 16V 20% 0402; Manufacturer Name: Generic
C4 C5 = CMP-00468-10: as C125 on sheet ETH_PHY
C7-C9 = CMP-00466-9: as C127 on sheet ETH_PHY
IC1 = CMP-00751-13: 802.15.4, Bluetooth, WiFi 802.11a/b/g/n/ac/ax Transceiver Module 2.4GHz ~ 5GHz Antenna Not Included, U.FL Surface Mount; Manufacturer Name: U-Blox
R1 R2 = CMP-00402-19: as R25 on sheet ETH_PHY
R3-R8 = CMP-00436-14: Resistor 100K ohm 50mW 1% 0201; Manufacturer Name: Generic
X1 = CMP-00731-8: as X1 on sheet ETH_PHY
X11 = CMP-00961-5: as X11 on sheet ETH_PHY
X12 = CMP-00962-5: LINO Secondary Connector; Manufacturer Part No.: 10164227-1001A1RLF; Manufacturer Name: Amphenol; Rows: 2

## Sheet RevisionHistory.SchDoc: Lino Verdin Adapter
size A3; Organization: Toradex AG; Address1: Ebenaustrasse 10; Address2: Horw; Address3: 6048; Address4: Switzerland; DocumentNumber: 1; Revision: V1.1; SheetNumber: 1; SheetTotal: 8
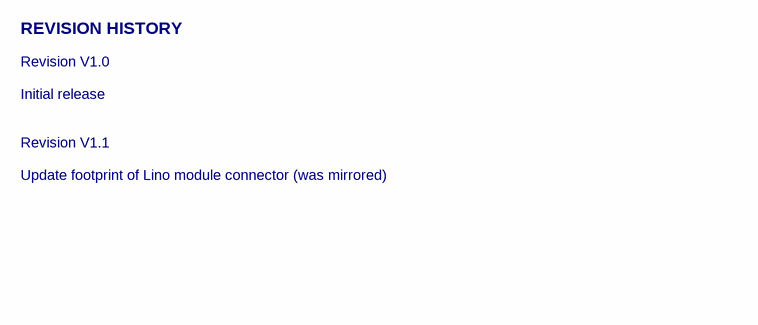
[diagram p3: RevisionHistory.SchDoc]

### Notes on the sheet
- REVISION HISTORY
- Revision V1.0
  Initial release
  Revision V1.1
  Update footprint of Lino module connector (was mirrored)

## Sheet I2C Devices.SchDoc: Lino Verdin Adapter
size A3; Organization: Toradex AG; Address1: Ebenaustrasse 10; Address2: Horw; Address3: 6048; Address4: Switzerland; DocumentNumber: 6; Revision: V1.1; SheetNumber: 6; SheetTotal: 8; PageSetup: Record=PageOptions¦CenterHorizontal=True¦CenterVertical=True¦PrintScale=0.73¦XCorrection=1.00¦YCorrection=1.00¦PrintKind=0¦BorderSize=5000000¦LeftOffset=0¦BottomOffset=0¦Orientation=2¦PaperLength=1000¦PaperWidth=1000¦Scale=100¦PaperSource=7¦PrintQuality=-4¦MediaType=1¦DitherType=10¦PaperKind=A4¦PrintScaleMode=1
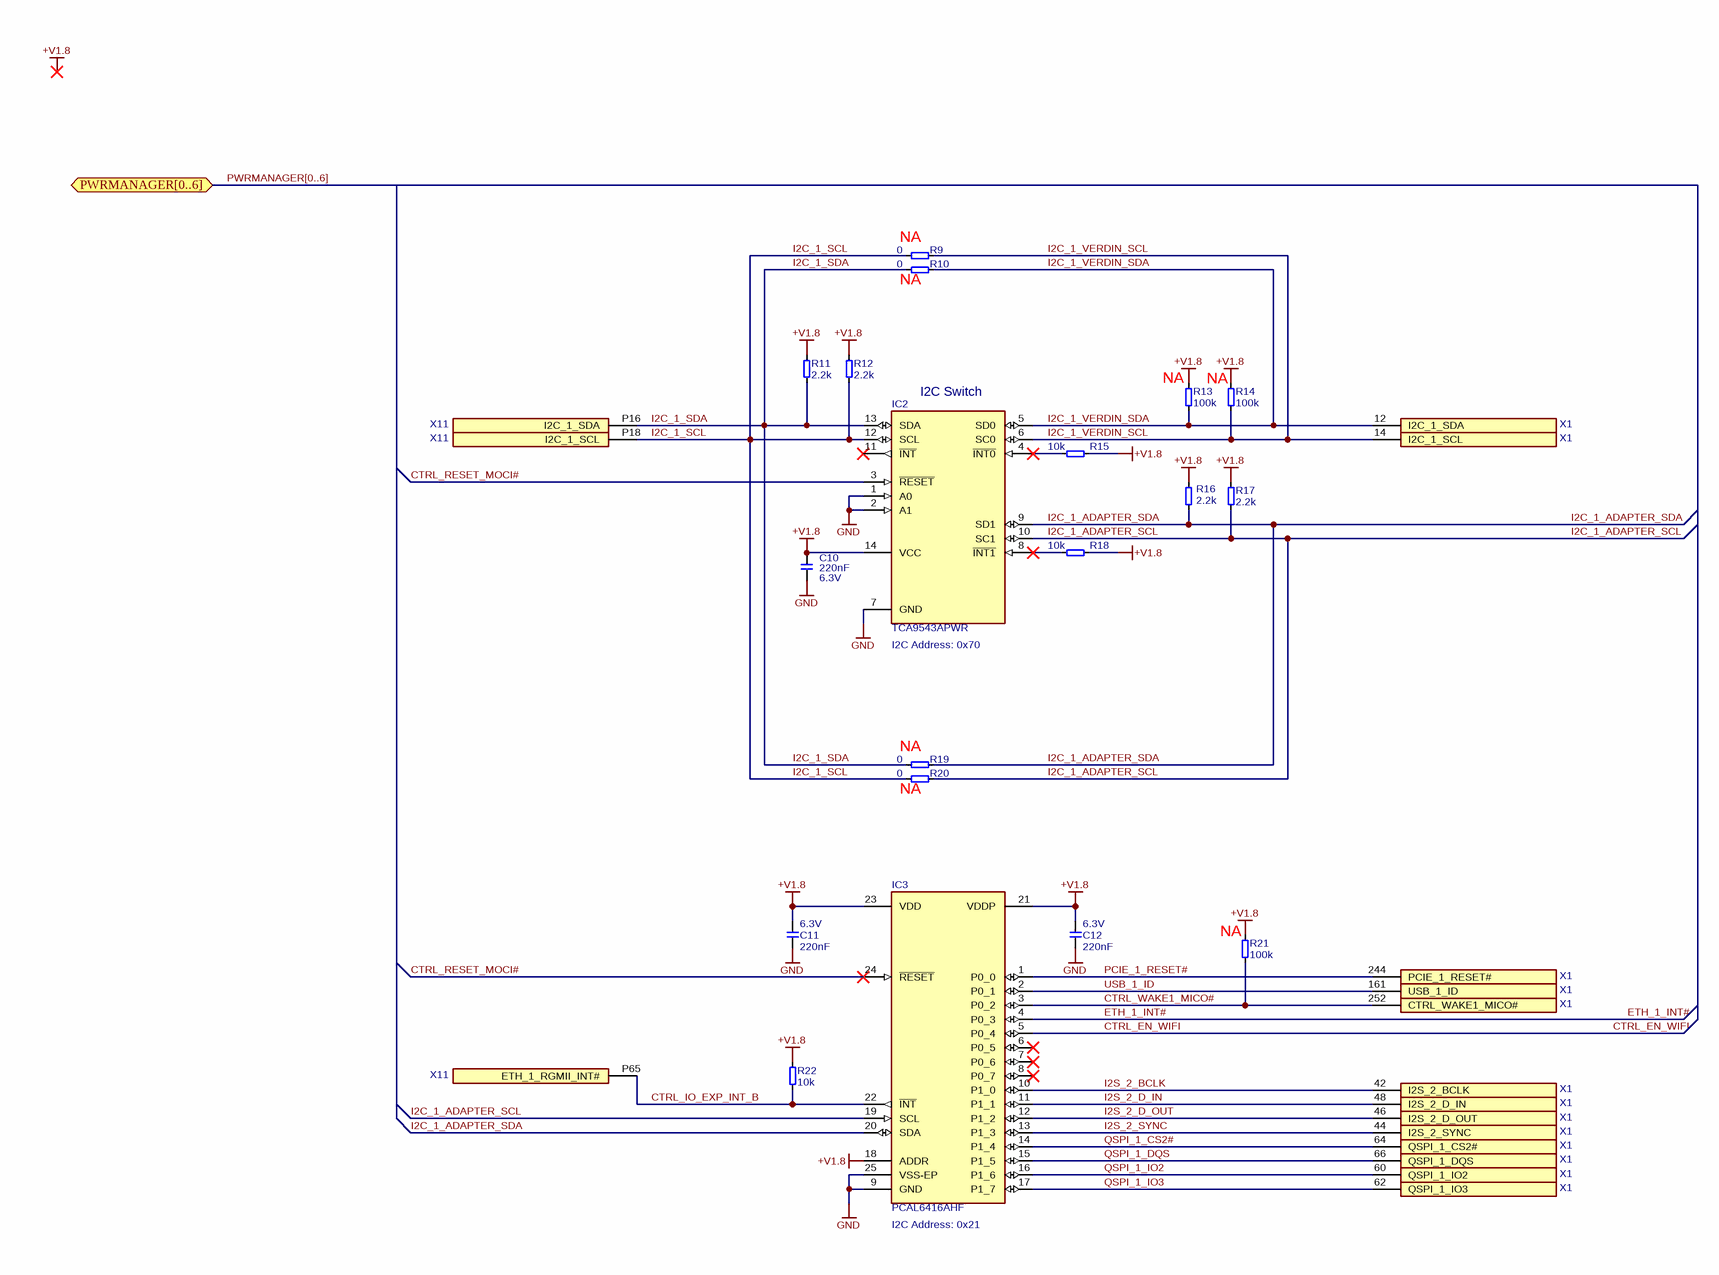
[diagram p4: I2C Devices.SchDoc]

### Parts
C10  value 220nF  Rating: 6.3V  [CAPC60X30X33L15L]  (hidden comment: C-X5R-220n-6.3V-20%-0201)
C11  value 220nF  Rating: 6.3V  [CAPC60X30X33L15L]  (hidden comment: C-X5R-220n-6.3V-20%-0201)
C12  value 220nF  Rating: 6.3V  [CAPC60X30X33L15L]  (hidden comment: C-X5R-220n-6.3V-20%-0201)
IC2  Manufacturer Part No.: TCA9543APWR  [TSSOP14P65_440X500X120L60X25]  (hidden comment: IC-TI-TCA9543APWR)
IC3  Manufacturer Part No.: PCAL6416AHF  [QFN24P50_400X400X80L40X20T200X200L_SoM]  (hidden comment: NXP-PCAL6416AHF-HVQFN24)
R9  value 0  [RESC60X30X33L15L]  (hidden comment: R-0R-50mW-5%-0201)
R10  value 0  [RESC60X30X33L15L]  (hidden comment: R-0R-50mW-5%-0201)
R11  value 2.2k  [RESC60X30X33L15L]  (hidden comment: R-2.2K-50mW-5%-0201)
R12  value 2.2k  [RESC60X30X33L15L]  (hidden comment: R-2.2K-50mW-5%-0201)
R13  value 100k  [RESC60X30X33L15L]  (hidden comment: R-100K-50mW-1%-0201)
R14  value 100k  [RESC60X30X33L15L]  (hidden comment: R-100K-50mW-1%-0201)
R15  value 10k  [RESC60X30X33L15L]  (hidden comment: R-10K-50mW-1%-0201)
R16  value 2.2k  [RESC60X30X33L15L]  (hidden comment: R-2.2K-50mW-5%-0201)
R17  value 2.2k  [RESC60X30X33L15L]  (hidden comment: R-2.2K-50mW-5%-0201)
R18  value 10k  [RESC60X30X33L15L]  (hidden comment: R-10K-50mW-1%-0201)
R19  value 0  [RESC60X30X33L15L]  (hidden comment: R-0R-50mW-5%-0201)
R20  value 0  [RESC60X30X33L15L]  (hidden comment: R-0R-50mW-5%-0201)
R21  value 100k  [RESC60X30X33L15L]  (hidden comment: R-100K-50mW-1%-0201)
R22  value 10k  [RESC60X30X33L15L]  (hidden comment: R-10K-50mW-1%-0201)
X1  CON-SODIMM-DDR4-TEST  [SODIMM_DDR4_no_Module]  (value not drawn)  (parts F,G,S,Y,104,157,171,172,173,174,180,181,182 of 260)  (no BOM)
X11  CON-LINO-P-CARRIER  [HIROSE_DF40C_100DS_LINO_CARRIER_PRIMARY]  (value not drawn)  (parts 33,58,59 of 100)

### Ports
PWRMANAGER[0..6] (bidir)

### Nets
+V1.8: C10.2 C11.2 C12.2 IC2.14(VCC) IC3.18(ADDR) IC3.21(VDDP) IC3.23(VDD) R11.2 R12.2 R13.1 R14.1 R15.2 R16.2 R17.2 R18.2 R21.1 R22.2
GND: C10.1 C11.1 C12.1 IC2.1(A0) IC2.2(A1) IC2.7(GND) IC3.9(GND) IC3.25(VSS-EP)
CTRL_EN_WIFI: IC3.5(P0_4)
CTRL_IO_EXP_INT_B: IC3.22(~{INT}) R22.1 X11.P65(ETH_1_RGMII_INT#)
CTRL_RESET_MOCI#: IC2.3(~{RESET}) IC3.24(~{RESET})
CTRL_WAKE1_MICO#: IC3.3(P0_2) R21.2 X1.252(CTRL_WAKE1_MICO#)
ETH_1_INT#: IC3.4(P0_3)
I2C_1_ADAPTER_SCL: IC2.10(SC1) IC3.19(SCL) R17.1 R20.2
I2C_1_ADAPTER_SDA: IC2.9(SD1) IC3.20(SDA) R16.1 R19.2
I2C_1_SCL: IC2.12(SCL) R9.1 R12.1 R20.1 X11.P18(I2C_1_SCL)
I2C_1_SDA: IC2.13(SDA) R10.1 R11.1 R19.1 X11.P16(I2C_1_SDA)
I2C_1_VERDIN_SCL: IC2.6(SC0) R9.2 R14.2 X1.14(I2C_1_SCL)
I2C_1_VERDIN_SDA: IC2.5(SD0) R10.2 R13.2 X1.12(I2C_1_SDA)
I2S_2_BCLK: IC3.10(P1_0) X1.42(I2S_2_BCLK)
I2S_2_D_IN: IC3.11(P1_1) X1.48(I2S_2_D_IN)
I2S_2_D_OUT: IC3.12(P1_2) X1.46(I2S_2_D_OUT)
I2S_2_SYNC: IC3.13(P1_3) X1.44(I2S_2_SYNC)
PCIE_1_RESET#: IC3.1(P0_0) X1.244(PCIE_1_RESET#)
QSPI_1_CS2#: IC3.14(P1_4) X1.64(QSPI_1_CS2#)
QSPI_1_DQS: IC3.15(P1_5) X1.66(QSPI_1_DQS)
QSPI_1_IO2: IC3.16(P1_6) X1.60(QSPI_1_IO2)
QSPI_1_IO3: IC3.17(P1_7) X1.62(QSPI_1_IO3)
USB_1_ID: IC3.2(P0_1) X1.161(USB_1_ID)
NetIC2_4: IC2.4(~{INT0}) R15.1
NetIC2_8: IC2.8(~{INT1}) R18.1

Not connected (* = marked no-connect by the designer): IC2 11(~{INT})*; IC3 6(P0_5)* 7(P0_6)* 8(P0_7)*

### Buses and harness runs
bus PWRMANAGER[0..6] = port PWRMANAGER[0..6]

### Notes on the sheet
- (near R9) NA
- (near R10) NA
- (near IC2) I2C Switch
- (near R13) NA
- NA
- (near IC2) I2C Address: 0x70
- (near R19) NA
- (near R20) NA
- (near R21) NA
- (near IC3) I2C Address: 0x21
- Labels drawn without touching a wire or pin: +V1.8

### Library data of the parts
C10-C12 = CMP-00477-9: Capacitor Ceramic X5R 220nF 6.3V 20% 0201; Manufacturer Name: Generic
IC2 = CMP-00864-2: 2-channel 1.65- to 5.5-V I2C/SMBus switch with interrupt, reset & voltage translation; Manufacturer Name: TI; Max Supply Voltage: 5.5V; Nominal Supply Voltage: 1.8V; Min Supply Voltage: 1.65V
IC3 = CMP-00184-11: Low-voltage translating 16-bit I2C-bus/SMBus I/O expander; Manufacturer Name: NXP
R9 R10 R19 R20 = CMP-00402-19: as R25 on sheet ETH_PHY
R11 R12 R16 R17 = CMP-00441-14: Resistor 2.2K ohm 50mW 5% 0201; Manufacturer Name: Generic
R13 R14 R21 = CMP-00436-14: as R3 on sheet Wi-Fi
R15 R18 R22 = CMP-00426-16: as R24 on sheet ETH_PHY
X1 = CMP-00731-8: as X1 on sheet ETH_PHY
X11 = CMP-00961-5: as X11 on sheet ETH_PHY

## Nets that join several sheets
+V1.8: ETH_PHY (27 pins), Wi-Fi (11 pins), I2C Devices (17 pins)
GND: ETH_PHY (45 pins), Wi-Fi (32 pins), I2C Devices (8 pins)
CTRL_EN_WIFI: Wi-Fi (IC1.J3), I2C Devices (IC3.5)
CTRL_RESET_MOCI#: ETH_PHY (IC17.43), Wi-Fi (R1.2 R2.2), I2C Devices (IC2.3 IC3.24)
ETH_1_INT#: ETH_PHY (IC17.44 R24.1), I2C Devices (IC3.4)

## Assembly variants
0185 Verdin Lino Adapter V1.1A.001: not fitted R1 R2 R7 R8 R9 R10 R13 R14 R19 R20 R21 R26 R29 R32 R34 R50 R53 R84 R87 R89 R90 R91 R93 R94 R95 R96 R97 R98 R123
